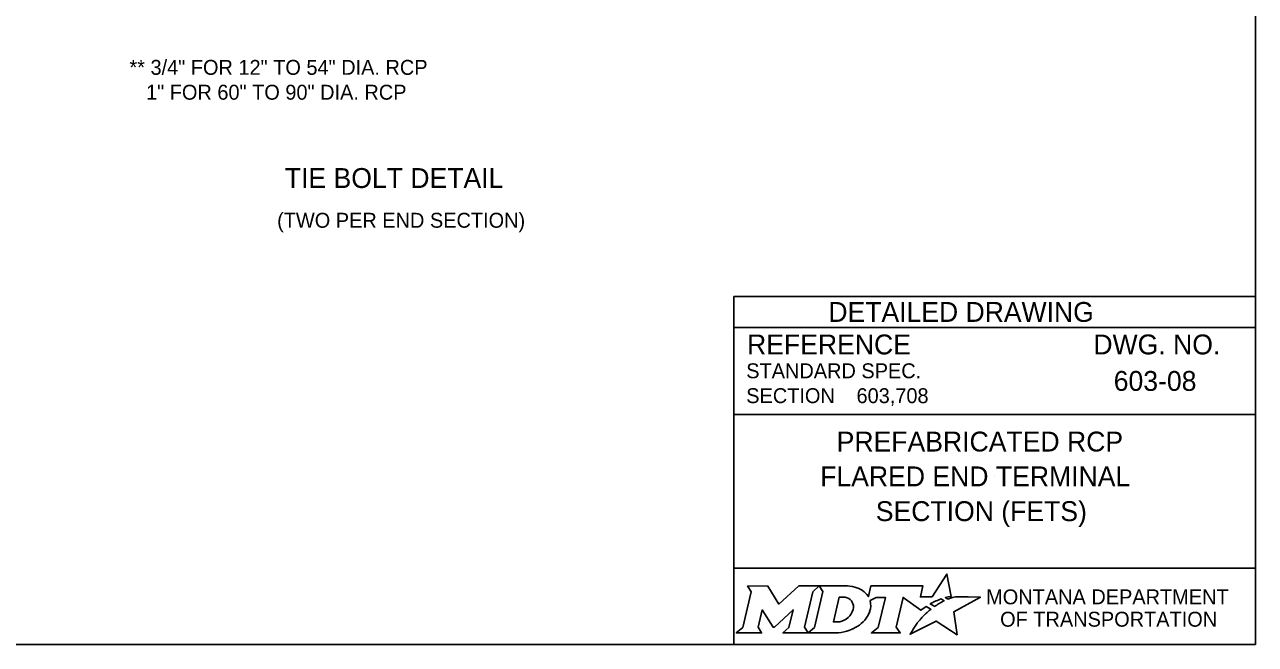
# Model space of a CAD drawing. Extents: x 49991.4 to 50021, y 49987.6 to 50011.4.
# Drawn here: x 50011.795 to 50016.75, y 49987.799 to 49990.292 of the extents above; entities that cross this region are included whole.
import ezdxf

# ---------------------------------------------------------------- set-up
doc = ezdxf.new("R2010")
doc.units = 0
for name, color, linetype in [('Default', 7, 'Continuous'), ('Level 1', 7, 'Continuous'), ('Level 2', 7, 'Continuous'), ('Level 5', 7, 'Continuous')]:
    doc.layers.add(name, color=color, linetype=linetype)

msp = doc.modelspace()

# ---------------------------------------------------------------- linework, layer by layer
at = {"layer": 'Default'}
for points in [[(50015.5126, 49987.9811), (50015.5023, 49987.9867), (50015.5139, 49987.9895), (50015.5255, 49987.9915), (50015.5081, 49988.0816), (50015.4486, 49987.9903), (50015.4013, 49987.9896), (50015.4116, 49988.0337), (50015.2024, 49988.0338), (50015.1923, 49987.9913), (50015.1865, 49987.9996)], [(50014.7056, 49988.0338), (50014.7197, 49988.0104), (50014.6862, 49987.8671), (50014.6605, 49987.8446), (50014.7621, 49987.8446), (50014.7486, 49987.8674), (50014.7648, 49987.9375), (50014.8085, 49987.8685), (50014.8138, 49987.8685), (50014.8889, 49987.938), (50014.8725, 49987.8669), (50014.8478, 49987.8449), (50014.9494, 49987.8449), (50014.9356, 49987.8682), (50014.9688, 49988.0106)], [(50014.9688, 49988.0106), (50014.9941, 49988.0338), (50014.9117, 49988.0338), (50014.8321, 49987.9608), (50014.7876, 49988.0335), (50014.7056, 49988.0338)], [(50015.1077, 49988.0338), (50014.9941, 49988.0338), (50015.0088, 49988.0109), (50014.9749, 49987.8671), (50014.9494, 49987.8449), (50015.06, 49987.8449)], [(50015.1317, 49987.9471), (50015.1305, 49987.939), (50015.1273, 49987.9297), (50015.1231, 49987.9215), (50015.1175, 49987.914), (50015.111, 49987.9071), (50015.1031, 49987.9008), (50015.0948, 49987.8961), (50015.0857, 49987.8922), (50015.0766, 49987.8899), (50015.0674, 49987.889), (50015.0515, 49987.889), (50015.0751, 49987.989), (50015.0911, 49987.989), (50015.0987, 49987.9884), (50015.1063, 49987.9865), (50015.1129, 49987.9835), (50015.119, 49987.9793), (50015.1238, 49987.9743), (50015.1275, 49987.9683), (50015.1302, 49987.9621), (50015.1318, 49987.9547), (50015.1318, 49987.9517), (50015.1317, 49987.9471)], [(50015.1991, 49987.9747), (50015.2237, 49987.9878), (50015.2606, 49987.9878), (50015.232, 49987.8673), (50015.2045, 49987.8446), (50015.3207, 49987.8446), (50015.3037, 49987.8675), (50015.3319, 49987.9877), (50015.4032, 49987.936), (50015.4243, 49987.9511), (50015.444, 49987.9402)], [(50015.3882, 49987.8843), (50015.3729, 49987.8599), (50015.3682, 49987.8524), (50015.3624, 49987.8438), (50015.3601, 49987.8395), (50015.4654, 49987.8926), (50015.5493, 49987.8375), (50015.5362, 49987.9302), (50015.6431, 49987.9886), (50015.5938, 49987.9894), (50015.5637, 49987.9898), (50015.5429, 49987.9901), (50015.5361, 49987.9886), (50015.5312, 49987.9874), (50015.5228, 49987.9851), (50015.5126, 49987.9811)], [(50015.4622, 49987.9535), (50015.4598, 49987.9518), (50015.4415, 49987.9614), (50015.4518, 49987.9671), (50015.4559, 49987.9693), (50015.4645, 49987.9733), (50015.4702, 49987.9759), (50015.4781, 49987.9789), (50015.4854, 49987.9816), (50015.4972, 49987.9742), (50015.4932, 49987.9721), (50015.4886, 49987.9696), (50015.4844, 49987.9674), (50015.4794, 49987.9645), (50015.4775, 49987.9634), (50015.4748, 49987.9618), (50015.4723, 49987.9604), (50015.47, 49987.9588), (50015.4674, 49987.957), (50015.4647, 49987.9552), (50015.4622, 49987.9535)], [(50015.4021, 49987.9004), (50015.4021, 49987.9004)], [(50015.1057, 49987.8522), (50015.1141, 49987.8548), (50015.1271, 49987.8602), (50015.1475, 49987.8712)]]:
    msp.add_lwpolyline(points, dxfattribs=at)
for centre, radius, start, end in [((50015.0868, 49987.9727), 0.1183, 300.9103, 339.1383), ((50015.1308, 49987.9554), 0.0709, 339.5329, 15.8582)]:
    msp.add_arc(centre, radius, start, end, dxfattribs=at)
for centre, major_axis, ratio, start_param, end_param in [((50015.1056, 49987.9864), (0.0834, -0.0037), 0.568097, 0.61298, 1.570796), ((50015.1612, 49987.9937), (0.0361, -0.0295), 0.469099, 1.225588, 1.570796), ((50015.4329, 49987.9305), (-0.0112, -0.0097), 0.021651, 3.157348, 6.283185), ((50015.3952, 49987.8923), (-0.00694, -0.00806), 0.008222, 0, 3.137361), ((50015.4119, 49987.9106), (-0.0098, -0.0102), 0.016458, 3.141593, 6.279097), ((50015.0603, 49987.9932), (0, 0.1484), 0.987302, 3.139398, 3.456847)]:
    msp.add_ellipse(centre, major_axis=major_axis, ratio=ratio, start_param=start_param, end_param=end_param, dxfattribs=at)
at = {"layer": 'Level 1'}
msp.add_lwpolyline([(49999.3835, 49998.9992), (50016.7501, 49998.9992), (50016.7501, 49987.7988), (49999.3835, 49987.7988)], close=True, dxfattribs=at)
at = {"layer": 'Level 2'}
for p, q in [((50016.7501, 49987.7988), (50016.7501, 49998.9992)), ((49999.3835, 49987.7988), (50016.7501, 49987.7988))]:
    msp.add_line(p, q, dxfattribs=at)
at = {"layer": 'Level 5'}
for p, q in [((50016.7501, 49989.1988), (50014.6501, 49989.1988)), ((50014.6501, 49989.1988), (50014.6501, 49987.7988)), ((50016.7501, 49989.0738), (50014.6501, 49989.0738)), ((50016.3862, 49988.8587), (50016.3862, 49988.8587)), ((50015.1444, 49988.7993), (50015.1444, 49988.7993)), ((50016.7501, 49988.7238), (50014.6501, 49988.7238)), ((50015.7001, 49988.4747), (50015.7001, 49988.4747)), ((50016.7501, 49988.1057), (50014.6501, 49988.1057))]:
    msp.add_line(p, q, dxfattribs=at)

# ---------------------------------------------------------------- texts
at = {"layer": 'Default'}
for s, p in [('MONTANA DEPARTMENT', (50015.6663, 49987.96)), ('OF TRANSPORTATION', (50015.7225, 49987.87))]:
    msp.add_text(s, height=0.06, dxfattribs=at).set_placement(p)
at = {"layer": 'Level 2'}
for s, height, p in [('** 3/4" FOR 12" TO 54" DIA. RCP', 0.06, (50012.2174, 49990.0902)), ('   1" FOR 60" TO 90" DIA. RCP', 0.06, (50012.2174, 49989.9902)), ('TIE BOLT DETAIL', 0.08, (50012.8429, 49989.635)), ('(TWO PER END SECTION)', 0.06, (50012.8119, 49989.475)), ('603-08', 0.08, (50016.1798, 49988.8187)), ('603,708', 0.06, (50015.1444, 49988.7693)), ('PREFABRICATED RCP', 0.08, (50015.0644, 49988.5747)), ('FLARED END TERMINAL', 0.08, (50014.9981, 49988.4347)), ('SECTION (FETS)', 0.08, (50015.222, 49988.2947))]:
    msp.add_text(s, height=height, dxfattribs=at).set_placement(p)
at = {"layer": 'Level 5'}
for s, height, p in [('DETAILED DRAWING', 0.0799, (50015.0311, 49989.0963)), ('REFERENCE', 0.08, (50014.7037, 49988.9654)), ('DWG. NO.', 0.08, (50016.0979, 49988.9654)), ('STANDARD SPEC.', 0.06, (50014.7004, 49988.8694)), ('SECTION', 0.06, (50014.7004, 49988.7694))]:
    msp.add_text(s, height=height, dxfattribs=at).set_placement(p)

doc.saveas('drawing.dxf')
